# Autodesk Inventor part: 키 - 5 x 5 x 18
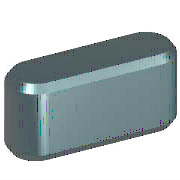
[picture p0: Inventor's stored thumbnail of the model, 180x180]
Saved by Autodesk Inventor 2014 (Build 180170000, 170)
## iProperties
Created: 2012-02
Part Number: 키 - 5 x 5 x 18
Material: 강철, 연강
Description: 키 및 해당 키홈
Document SubType Name: Modeling
Standard: KS B 1311
Designer: mduedu
Standards Organization: KS
Language: ko-KR
Size Designation: 5 x 5 x 18
Categories: <MemberInstance><Categories><Category DisplayName="샤프트 부품" InternalName="7f7aeb1f-a693-4053-b835-cee3144e0d98" Mnemonic="SHFT"><Category DisplayName="키" Interna
Density: 7.86 g/cm^3
Mass: 3.27476 g
Surface Area: 3.57848 cm^2
Volume: 0.416636 cm^3
Appearance: 노란색
IsCustomPart: 1
Author: mduedu
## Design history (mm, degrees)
workplane "Work Plane1"
workplane "Work Plane2"
sketch "스케치1"
  geometry: L1 (2.5, 2.5)-(15.5, 2.5); L2 (15.5, -2.5)-(2.5, -2.5); L3 (0, 9.4)-(0, -7.4) reference; L4 (-5, 0)-(30, 0) reference; L5 (18, 0)-(18, 7); A1 r 2.5 centre (2.5, 0) between (2.5, 2.5) and (2.5, -2.5); A2 r 2.5 centre (15.5, 0) between (15.5, -2.5) and (15.5, 2.5)
  constraints: 6 end point, 5 point on circle, 4 tangent, 3 point on line, 2 centre point, 1 horizontal, 1 parallel, 1 perpendicular
  dimensions: "d0" = 2.5 radius of A1 (= 0.5 x PB); "d13" = 2.5 radius of A2 (= 0.5 x PB); "d14" = 18 distance between parallel lines of L5 L3 (= NLG)
extrude "본체1" new body sketch "스케치1" taper "d3" = 0 deg; stored distance "d4" = 10
workplane "Work Plane3"
body "Solid1"
chamfer "모따기1" distance "d8" = 0.4 (= PHH); stored, may be unused: second distance "d9" = 0.4 (= PHH), angle "d15" = 45 deg
other parameters: "d1" = -3 (= -PNT), "d2" = 2 (= PH - PNT), "NLG" = 18 [user parameter; used in 3 equation terms], "PB" = 5 [user parameter; used in 2 equation terms], "PNT" = 3 [user parameter; used in 2 equation terms], "PH" = 5 [user parameter; used in 1 equation term], "PHH" = 0.4 [user parameter; used in 2 equation terms], "d10" = 0, "d16" = 0, "d17" = 0, "d18" = 0, "WDMIN" = 12 [user parameter], "PLB2" = 18 (= NLG) [user parameter], "WDMAX" = 17 [user parameter], "PLB1" = 18 (= NLG) [user parameter], "RR" = 0.16 [user parameter], "PUEB" = 2.3 [user parameter]
